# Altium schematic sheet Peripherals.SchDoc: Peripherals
size A4; DocumentNumber: MB1167; Revision: B.1; SheetNumber: 12; SheetTotal: 17; Project: STM327x6G-EVAL
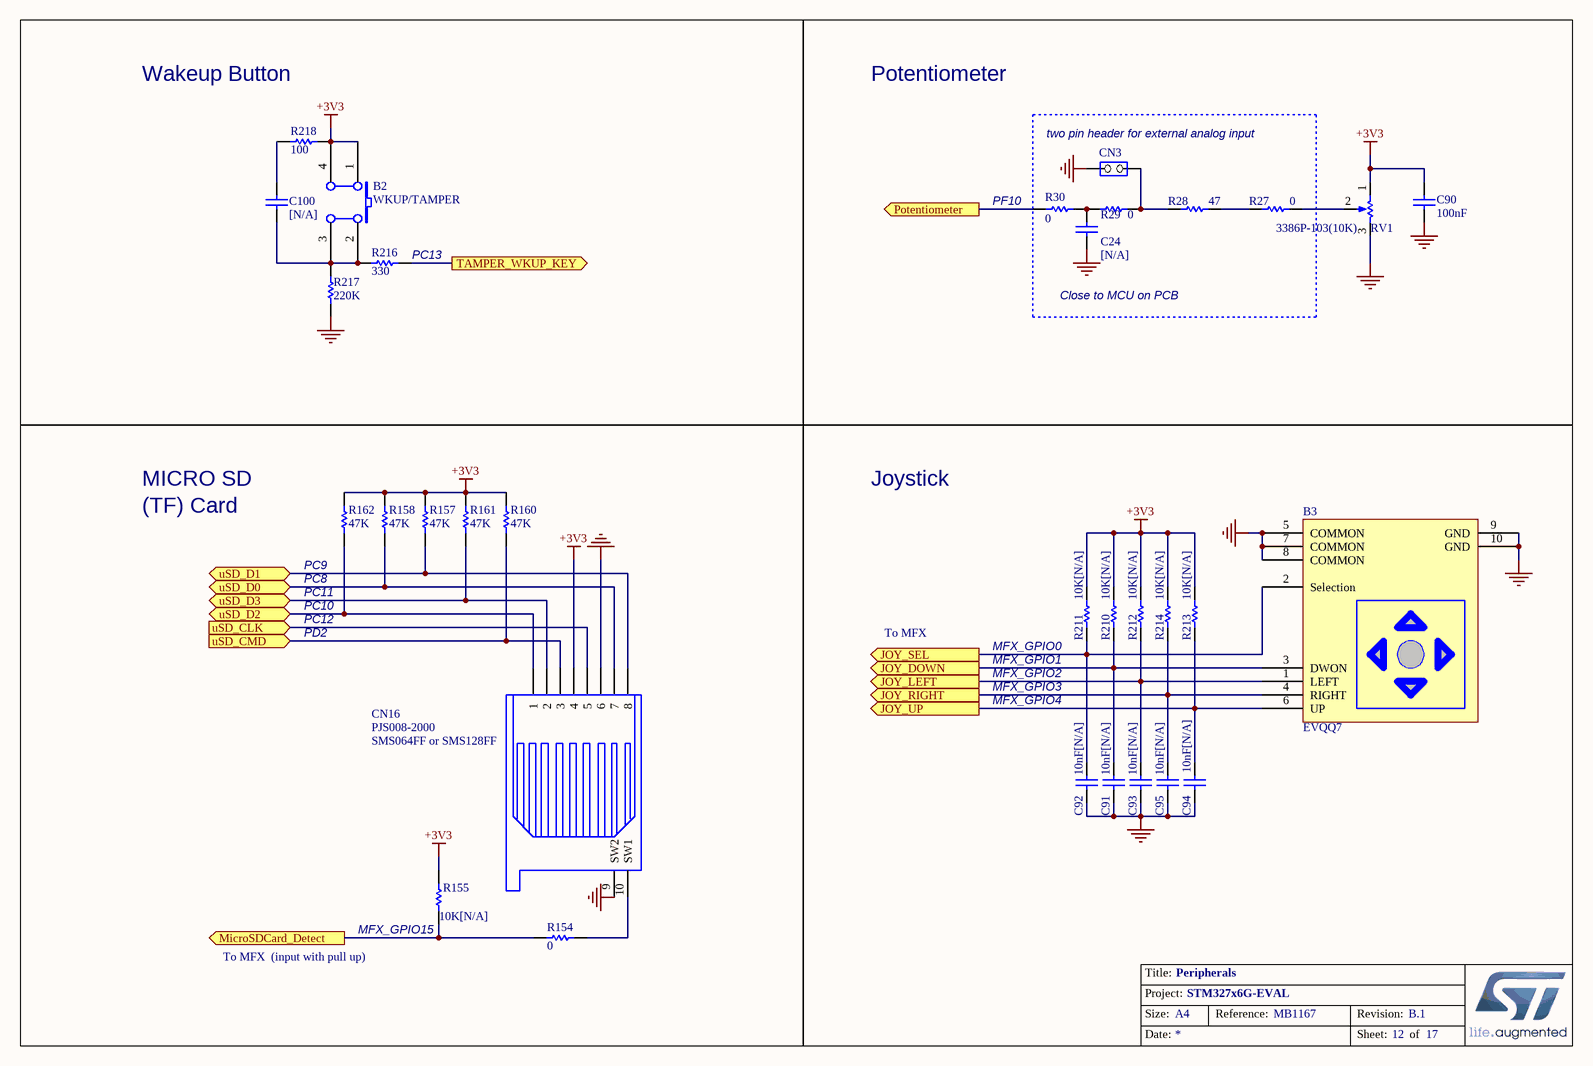
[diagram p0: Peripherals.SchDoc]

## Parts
B2  WKUP/TAMPER  [PB10]
B3  EVQQ7  [SW-JOY]
C24  [N/A]  [0603C]
C90  100nF  [0603C]
C91  10nF[N/A]  [0603C]
C92  10nF[N/A]  [0603C]
C93  10nF[N/A]  [0603C]
C94  10nF[N/A]  [0603C]
C95  10nF[N/A]  [0603C]
C100  [N/A]  [0603C]
CN3  (no value)  [SIP2]
CN16  PJS008-2000  [MSD_PJS008_]
R27  0  [0603R]
R28  47  [0603R]
R29  0  [0603R]
R30  0  [0603R]
R154  0  [0603R]
R155  10K[N/A]  [0603R]
R157  47K  [0603R]
R158  47K  [0603R]
R160  47K  [0603R]
R161  47K  [0603R]
R162  47K  [0603R]
R210  10K[N/A]  [0603R]
R211  10K[N/A]  [0603R]
R212  10K[N/A]  [0603R]
R213  10K[N/A]  [0603R]
R214  10K[N/A]  [0603R]
R216  330  [0603R]
R217  220K  [0603R]
R218  100  [0603R]
RV1  3386P-103(10K)  [3386P]

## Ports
JOY_DOWN (out), JOY_LEFT (out), JOY_RIGHT (out), JOY_SEL (out), JOY_UP (out), MicroSDCard_Detect (out), Potentiometer (out), TAMPER_WKUP_KEY (out), uSD_CLK (in), uSD_CMD (in), uSD_D0 (bidir), uSD_D1 (bidir), uSD_D2 (bidir), uSD_D3 (bidir)

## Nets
+3V3: B2.1(A0) B2.4(A1) C90.1 CN16.4 R155.2 R157.1 R158.1 R160.1 R161.1 R162.1 R210.1 R211.1 R212.1 R213.1 R214.1 R218.1 RV1.1(BOT)
GND: B3.5(COMMON) B3.7(COMMON) B3.8(COMMON) B3.9(GND) B3.10(GND) C24.1 C90.2 C91.1 C92.1 C93.1 C94.1 C95.1 CN3.2(NO) CN16.6 CN16.9(SW2) R217.2 RV1.3(TOP)
JOY_DOWN: B3.3(DWON) C91.2 R210.2 ; port JOY_DOWN
JOY_LEFT: B3.1(LEFT) C93.2 R212.2 ; port JOY_LEFT
JOY_RIGHT: B3.4(RIGHT) C95.2 R214.2 ; port JOY_RIGHT
JOY_SEL: B3.2(Selection) C92.2 R211.2 ; port JOY_SEL
JOY_UP: B3.6(UP) C94.2 R213.2 ; port JOY_UP
MicroSDCard_Detect: R154.1 R155.1 ; port MicroSDCard_Detect
Potentiometer: R30.2 ; port Potentiometer
TAMPER_WKUP_KEY: R216.2 ; port TAMPER_WKUP_KEY
uSD_CLK: CN16.5 ; port uSD_CLK
uSD_CMD: CN16.3 R160.2 ; port uSD_CMD
uSD_D0: CN16.7 R158.2 ; port uSD_D0
uSD_D1: CN16.8 R157.2 ; port uSD_D1
uSD_D2: CN16.1 R162.2 ; port uSD_D2
uSD_D3: CN16.2 R161.2 ; port uSD_D3
NetB2_2: B2.2(B0) B2.3(B1) C100.2 R216.1 R217.1
NetC24_2: C24.2 R29.1 R30.1
NetC100_1: C100.1 R218.2
NetCN3_1: CN3.1(COMMON) R28.1 R29.2
NetCN16_10: CN16.10(SW1) R154.2
NetR27_1: R27.1 R28.2
NetR27_2: R27.2 RV1.2(TAP)

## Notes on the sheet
- Wakeup Button
- Potentiometer
- (near CN3) two pin header for external analog input
- (near R216) PC13
- (near R30) PF10
- Close to MCU on PCB
- MICRO SD
- (TF) Card
- Joystick
- (near R162) PC8
- (near R162) PC9
- PC11
- PC10
- PC12
- PD2
- To MFX
- (near R211) MFX_GPIO0
- MFX_GPIO1
- MFX_GPIO2
- MFX_GPIO3
- MFX_GPIO4
- (near CN16) SMS064FF or SMS128FF
- (near R155) MFX_GPIO15
- To MFX  (input with pull up)

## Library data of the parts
B2 = SW PUSHBUTTON: SE PUSHBUTTON
C24 = cap: Capacitor; Value: 100pF
C90-C95 C100 = CAP: Capacitor; Value: 100pF
CN3 = JP2
CN16 = SMS016AFA5E
R27-R30 R154 R155 R216 R218 = Res1: Resistor; Value: 1K
R157 R158 R160-R162 R210-R214 R217 = res1: Resistor; Value: 1K
RV1 = RV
